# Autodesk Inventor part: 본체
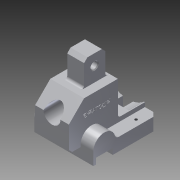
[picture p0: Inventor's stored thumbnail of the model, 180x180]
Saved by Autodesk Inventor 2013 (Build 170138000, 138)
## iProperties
Created: 2016-11
Part Number: 본체
Material: 알루미늄 6061
Document SubType Name: Modeling
Designer: 나래
Density: 2.71 g/cm^3
Mass: 462.907 g
Surface Area: 317.29 cm^2
Volume: 170.814 cm^3
Author: 나래
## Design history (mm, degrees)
sketch "스케치1"
  geometry: L1 (20, 18)-(-20, 18); L2 (-20, 18)-(-20, -30); L3 (-20, -30)-(20, -30); L4 (20, -30)-(20, 18); 2 further points
  constraints: 8 end point, 2 parallel, 1 horizontal, 1 midpoint, 1 perpendicular, 1 vertical alignment
  dimensions: "d0" = 30 distance from line of L3 point (0, 0); "d1" = 48 distance of L3.end L1.start; "d2" = 40 distance of L1.start L1.end
extrude "돌출1" new body sketch "스케치1" stored distance "d3" = 58; taper "d4" = 0 deg
sketch "스케치2"
  geometry: L1 (-30, -29)-(-30, 29) reference; L2 (-30, -29)-(18, -29) reference; L3 (18, 29)-(-30, 29) reference; L4 (-27, 2)-(-42, 2); L5 (-42, -8)-(-42, -61); L6 (-42, -61)-(-27, -61); L7 (-27, -61)-(-27, -11); L8 (-27, 15)-(-42, 15); L9 (-42, 15)-(-42, 12); L10 (-42, 12)-(-35, 12); L11 (-35, 12)-(-35, -8); L12 (-35, -8)-(-42, -8); L13 (-27, -11)-(-27, 2); A1 r 13 centre (-27, 2) between (-27, -11) and (-27, 15); 1 further point
  constraints: 20 end point, 7 perpendicular, 3 parallel, 2 point on circle, 1 centre point, 1 coincident, 1 horizontal, 1 tangent, 1 other
  dimensions: "d5" = 90 distance between parallel lines of L6 L3; "d6" = 42 distance from line of L5 point (0, 0); "d7" = 15 distance between parallel lines of L5 L7; "d8" = 63 distance between parallel lines of L6 L4; "d9" = 13 radius of A1; "d11" = 3 distance between parallel lines of L8 L10; "d12" = 7 distance of L9.end L10.end; "d13" = 15 distance between parallel lines of L9 L7
extrude "돌출2" join sketch "스케치2" stored distance "d14" = 70; taper "d15" = 0 deg
sketch "스케치3"
  geometry: L1 (70, -15)-(0, -15) reference; L2 (15, -15)-(55, -15); L3 (55, -15)-(55, 5); L4 (55, 5)-(15, 5); L5 (15, 5)-(15, -15); L6 (35, 27)-(35, -15); L7 (15, 45)-(15, 0) reference; L8 (55, 0)-(55, 45) reference
  constraints: 10 end point, 2 parallel, 2 perpendicular, 2 point on line, 1 horizontal, 1 midpoint, 1 other
  dimensions: "d16" = 20 distance of L4.end L2.start
extrude "돌출3" join sketch "스케치3" distance "d18" = 50; taper "d19" = 0 deg
sketch "스케치4"
  geometry: L1 (70, 0)-(0, 0) reference; L2 (35, 42)-(35, 0); L3 (29, 13.627)-(29, 0); L4 (41, 13.627)-(41, 0); L5 (29, 0)-(41, 0); A1 r 29 centre (35, 42) between (41, 13.627) and (29, 13.627); 1 further point
  constraints: 8 end point, 2 parallel, 2 point on circle, 2 point on line, 1 centre point, 1 coincident, 1 collinear, 1 midpoint, 1 perpendicular, 1 other
  dimensions: "d20" = 29 radius of A1; "d22" = 12 distance between parallel lines of L4 L3
extrude "돌출4" cut sketch "스케치4" distance "d23" = 18; taper "d24" = 0 deg
chamfer "모따기1" distance "d25" = 18; stored, may be unused: second distance "d26" = 2, angle "d27" = 45 deg
chamfer "모따기2" distance "d28" = 4; stored, may be unused: second distance "d29" = 2, angle "d30" = 45 deg
sketch "스케치5"
  geometry: 1 further point
hole "구멍1" sketch "스케치5" at (0, 0) diameter "d31" = 20; stored, may be unused: countersink angle "d35" = 90 deg, drill point angle "d37" = 118 deg; dims "d32" = 6, "d33" = 29, "d34" = 7, "d36" = 8
sketch "스케치6"
  geometry: L1 (18, -29)-(18, 11) reference; L2 (14.5, -29)-(-14.5, -29) reference; L3 (18, -24)-(48, -24); L4 (48, -24)-(48, 1); L5 (48, 1)-(18, 1); L6 (18, 1)-(18, -24); L7 (-42, -61)-(-42, -8) reference; 1 further point
  constraints: 8 end point, 2 parallel, 1 horizontal, 1 perpendicular, 1 point on line
  dimensions: "d38" = 5 distance between parallel lines of L2 L3; "d39" = 25 distance of L3.end L4.end; "d43" = 90 distance between parallel lines of L7 L4
extrude "돌출5" join sketch "스케치6" stored distance "d41" = 20; taper "d42" = 0 deg
sketch "스케치7"
  geometry: L1 (-1, 48)-(-1, 18) reference; 2 further points
  dimensions: "d44" = 12.5 distance from line of L1 point (11.5, 35); "d45" = 35 vertical distance of point (0, 0) point (11.5, 35)
hole "구멍2" sketch "스케치7" at (11.5, 35) diameter "d46" = 8; stored, may be unused: countersink angle "d50" = 90 deg, drill point angle "d52" = 118 deg; dims "d47" = 6, "d48" = 29, "d49" = 7, "d51" = 8
chamfer "모따기3" distance "d53" = 4; stored, may be unused: second distance "d54" = 2, angle "d55" = 45 deg
chamfer "모따기4" distance "d56" = 1; stored, may be unused: second distance "d57" = 2, angle "d58" = 45 deg
fillet "모깎기1" dims "d59" = 5
node "작업 평면1"
sketch "스케치8"
  geometry: L1 (-70, -53)-(-55, -53) reference; L2 (-35, 8)-(-35, -53); 2 further points
  constraints: 2 end point, 1 perpendicular, 1 symmetric about line
  dimensions: "d61" = 18 distance from line of L1 point (-62.5, -35); "d62" = 55 distance of point (-7.5, -35) point (-62.5, -35)
hole "구멍3" sketch "스케치8" at (-7.5, -35), (-62.5, -35) diameter "d63" = 3.242; stored, may be unused: countersink angle "d67" = 90 deg, drill point angle "d69" = 118 deg; dims "d64" = 6, "d65" = 29, "d66" = 7, "d68" = 8
sketch "스케치9"
  geometry: L1 (44, 48)-(44, 8) reference; L2 (4, 48)-(44, 48) reference; 2 further points
  constraints: 1 other
  dimensions: "d70" = 18 distance from line of L2 point (19, 30); "d71" = 25 distance from line of L1 point (19, 30)
feature "엠보싱1" sketch "스케치9" dims "d0" = 30, "d1" = 48, "d2" = 40, "d72" = 0.5, "d73" = 0
fillet "모깎기2" dims "d74" = 3
chamfer "모따기5" distance "d75" = 5; stored, may be unused: second distance "d76" = 2, angle "d77" = 45 deg
node "솔리드1"
other parameters: "d60" = -15
